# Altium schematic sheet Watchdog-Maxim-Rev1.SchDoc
size Tabloid; Organization: Monterey Bay Aquarium Research Institute; Address1: 7700 Sandholdt Rd; Address2: Moss Landing, CA 95039-9644; CompanyName: MBARI
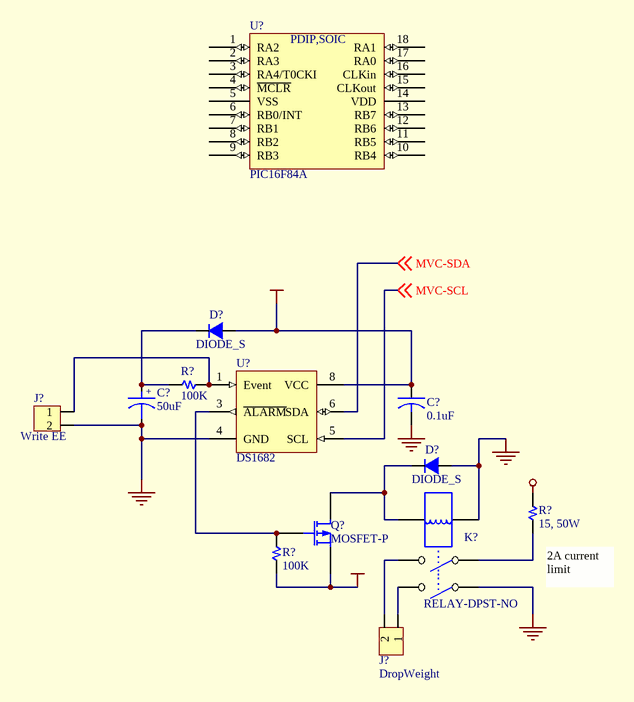
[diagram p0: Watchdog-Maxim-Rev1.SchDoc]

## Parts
(Parts that share a designator on the sheet are numbered #1, #2 ... from top to bottom, then left to right.)
C?#1  50uF
C?#2  0.1uF
D?#1  DIODE_S  [DIODE0.4]
D?#2  DIODE_S  [DIODE0.4]
J?#1  Write EE  [SIP2]
J?#2  DropWeight  [SIP2]
K?  RELAY-DPST-NO
Q?  MOSFET-P  [BCY-W3/H.8]
R?#1  100K  [AXIAL0.7]
R?#2  15, 50W  [AXIAL0.7]
R?#3  100K  [AXIAL0.7]
U?#1  PIC16F84A  [DIP18]
U?#2  DS1682  [SOIC-8]

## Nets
28.8VDC: R?#2.1
GND: C?#1.2 C?#2.2 D?#2.1(K) J?#1.2 K?.1 K?.5 U?#2.4(GND)
VCC: C?#2.1 D?#1.1(K) Q?.3(S) R?#3.1 U?#2.8(VCC)
MVC-SCL: U?#2.5(SCL) ; off-sheet MVC-SCL
MVC-SDA: U?#2.6(SDA) ; off-sheet MVC-SDA
NetC?#1_1: C?#1.1 D?#1.2(A) R?#1.1
NetD?#2_2: D?#2.2(A) K?.6 Q?.1(D)
NetJ?#1_1: J?#1.1 R?#1.2 U?#2.1(Event)
NetJ?#2_1: J?#2.1 K?.2
NetJ?#2_2: J?#2.2 K?.4
NetK?_3: K?.3 R?#2.2
NetQ?_2: Q?.2(G) R?#3.2 U?#2.3(~{ALARM})

Not connected (* = marked no-connect by the designer): U?#1 1(RA2) 2(RA3) 3(RA4/T0CKI) 4(~{MCLR}) 5(VSS) 6(RB0/INT) 7(RB1) 8(RB2) 9(RB3) 10(RB4) 11(RB5) 12(RB6) 13(RB7) 14(VDD) 15(CLKout) 16(CLKin) 17(RA0) 18(RA1)

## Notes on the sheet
- (near R?#2) 2A current limit

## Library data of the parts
C?#1 = CAPACITOR POL: Capacitor
C?#2 = CAPACITOR
D?#1 D?#2 = DIODE_S: Diode
J?#1 J?#2 = CON2: Connector
K? = RELAY-DPST-NO: Relay DPST-NO
Q? = MOSFET-P: P-Channel MOSFET; Manufacturer: Generic Components; Class: Discrete; SubClass: MOSFET - Low Power
R?#1-R?#3 = RESISTOR
U?#1 = PIC16F84A: PIC16F84A microcontroller PDIP,SOIC package
U?#2 = DS1682: Dallas Semi Elapsed Time Recorder with Alarm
